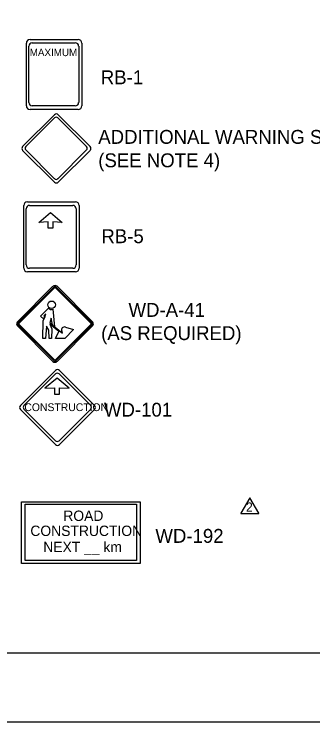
# Model space of a CAD drawing. Extents: x 1381 to 1597, y 125 to 404.
# Drawn here: x 1466.1 to 1512.9, y 124.9 to 235.9 of the extents above; entities that cross this region are included whole.
import ezdxf

# ---------------------------------------------------------------- set-up
doc = ezdxf.new("R2010")
doc.units = 0
for name, color, linetype in [('Level 1', 7, 'Continuous'), ('Level 10', 7, 'Continuous'), ('Level 2', 7, 'Continuous'), ('Level 44', 7, 'Continuous'), ('Level 60', 7, 'Continuous')]:
    doc.layers.add(name, color=color, linetype=linetype)

msp = doc.modelspace()

# ---------------------------------------------------------------- linework, layer by layer
at = {"layer": 'Level 1'}
for p, q in [((1472.17, 193.21), (1466.59, 187.63)), ((1472.3, 193.08), (1466.72, 187.51)), ((1478.25, 187.51), (1472.68, 193.08)), ((1478.38, 187.63), (1472.8, 193.21)), ((1472.42, 192.96), (1466.84, 187.39)), ((1478.13, 187.38), (1472.55, 192.96)), ((1472.23, 190.76), (1472.21, 190.76)), ((1466.59, 187), (1472.17, 181.43)), ((1466.72, 187.13), (1472.29, 181.56)), ((1466.84, 187.25), (1472.42, 181.68)), ((1472.55, 181.68), (1478.13, 187.25)), ((1472.67, 181.56), (1478.25, 187.13)), ((1472.8, 181.43), (1478.38, 187))]:
    msp.add_line(p, q, dxfattribs=at)
for points in [[(1470.76, 188.56), (1470.9, 188.44), (1470.74, 188.04), (1470.23, 188.52), (1471.45, 189.77)], [(1470.76, 188.56), (1470.9, 188.44), (1470.74, 188.04), (1470.23, 188.52), (1471.45, 189.77)], [(1471.18, 186.95), (1471, 185.05), (1470.58, 185.05), (1470.63, 187.78), (1470.74, 188.04), (1470.23, 188.52), (1471.45, 189.77)], [(1474.12, 186.83), (1475.4, 186.44), (1474.02, 185.05), (1472.56, 185.05), (1473.1, 186.1), (1471.69, 187.26), (1471.97, 186.52), (1471.93, 185.05), (1471.58, 185.05), (1471.52, 186.31), (1471.18, 186.95), (1471, 185.05), (1470.58, 185.05), (1470.63, 187.78), (1471.07, 188.88), (1470.76, 188.56)], [(1474.12, 186.83), (1475.4, 186.44), (1474.02, 185.05), (1472.56, 185.05), (1473.1, 186.1), (1471.69, 187.26), (1471.97, 186.52), (1471.93, 185.05), (1471.58, 185.05), (1471.52, 186.31), (1471.18, 186.95), (1471, 185.05), (1470.58, 185.05), (1470.63, 187.78), (1471.07, 188.88), (1470.76, 188.56)], [(1472.15, 189.6), (1472.43, 186.88), (1472.07, 187.18), (1471.86, 188.19), (1471.69, 187.48), (1473.68, 185.84), (1473.54, 186.2)], [(1472.15, 189.6), (1472.43, 186.88), (1472.07, 187.18), (1471.86, 188.19), (1471.69, 187.48), (1473.68, 185.84), (1473.54, 186.2)], [(1472.15, 189.6), (1472.43, 186.88), (1473.68, 185.84), (1473.54, 186.2)], [(1474.12, 186.83), (1475.4, 186.44), (1474.02, 185.05), (1472.56, 185.05), (1473.1, 186.1), (1471.69, 187.26), (1471.97, 186.52), (1471.93, 185.05), (1471.58, 185.05), (1471.52, 186.31), (1471.18, 186.95)]]:
    msp.add_lwpolyline(points, dxfattribs=at)
for points in [[(1470.76, 188.56), (1470.9, 188.44), (1471.07, 188.88)], [(1472.07, 187.17), (1471.86, 188.19), (1471.69, 187.48)]]:
    msp.add_lwpolyline(points, close=True, dxfattribs=at)
msp.add_circle((1471.96, 190.31), 0.591, dxfattribs=at)
msp.add_circle((1471.96, 190.31), 0.591, dxfattribs=at)
msp.add_circle((1471.96, 190.31), 0.591, dxfattribs=at)
for centre, radius, start, end in [((1472.49, 192.89), 0.446, 45, 134.9651), ((1472.49, 192.89), 0.27, 45, 134.9651), ((1472.49, 192.89), 0.0948, 45, 134.9651), ((1471.96, 190.31), 0.734, 226.3135, 284.9576), ((1471.96, 190.31), 0.734, 226.3135, 284.9576), ((1471.96, 190.31), 0.734, 226.3135, 284.9576), ((1466.91, 187.32), 0.446, 134.965, 225), ((1466.91, 187.32), 0.27, 134.965, 225), ((1478.06, 187.32), 0.27, 314.9651, 45), ((1478.06, 187.32), 0.446, 314.9651, 45), ((1466.91, 187.32), 0.0948, 134.965, 225), ((1473.98, 186.37), 0.475, 73.381, 201.0999), ((1473.98, 186.37), 0.475, 73.381, 201.0999), ((1473.98, 186.37), 0.475, 73.381, 201.0999), ((1478.06, 187.32), 0.0948, 314.9651, 45), ((1472.48, 181.75), 0.446, 225, 314.9652), ((1472.48, 181.75), 0.27, 225, 314.9652), ((1472.48, 181.75), 0.0948, 225, 314.9652)]:
    msp.add_arc(centre, radius, start, end, dxfattribs=at)
at = {"layer": 'Level 2'}
for points in [[(1467.22, 159.43), (1485.85, 159.43), (1485.85, 149.77), (1467.22, 149.77)], [(1467.81, 159.05), (1485.23, 159.05), (1485.23, 150.24), (1467.81, 150.24)]]:
    msp.add_lwpolyline(points, close=True, dxfattribs=at)
at = {"layer": 'Level 44'}
for p, q in [((1468.58, 231.89), (1476.1, 231.89)), ((1468, 221.52), (1468, 231.31)), ((1468.39, 222.01), (1468.39, 230.83)), ((1468.91, 231.35), (1475.67, 231.35)), ((1476.2, 230.83), (1476.2, 222.01)), ((1476.68, 231.31), (1476.68, 221.52)), ((1468.39, 222.01), (1468.39, 222.01)), ((1468, 221.51), (1468, 221.52)), ((1476.1, 220.93), (1468.58, 220.93)), ((1468.71, 221.17), (1468.71, 221.17)), ((1475.67, 221.49), (1468.91, 221.49)), ((1472.41, 220.1), (1467.42, 215.11)), ((1477.99, 215.11), (1473, 220.1)), ((1467.91, 215.11), (1472.41, 219.6)), ((1472.94, 219.6), (1477.43, 215.11)), ((1467.42, 214.52), (1472.41, 209.53)), ((1467.42, 214.52), (1467.42, 214.52)), ((1472.41, 210.08), (1467.91, 214.58)), ((1477.43, 214.58), (1472.94, 210.08)), ((1473, 209.53), (1477.99, 214.52)), ((1468.17, 206.44), (1475.69, 206.44)), ((1467.59, 196.06), (1467.59, 205.86)), ((1467.98, 196.56), (1467.98, 205.38)), ((1468.5, 205.9), (1475.27, 205.9)), ((1475.79, 205.38), (1475.79, 196.56)), ((1476.27, 205.86), (1476.27, 196.06)), ((1467.98, 196.55), (1467.98, 196.56)), ((1467.59, 196.06), (1467.59, 196.06)), ((1475.69, 195.48), (1468.17, 195.48)), ((1475.27, 196.03), (1468.5, 196.03)), ((1472.56, 180.03), (1467.07, 174.54)), ((1478.69, 174.54), (1473.21, 180.03)), ((1467.62, 174.53), (1472.56, 179.47)), ((1472.8, 178.83), (1470.91, 177.23)), ((1474.69, 177.23), (1472.8, 178.83)), ((1473.14, 179.47), (1478.08, 174.53)), ((1470.91, 177.23), (1472.42, 177.31)), ((1472.42, 177.31), (1472.42, 176.31)), ((1473.18, 176.31), (1473.18, 177.31)), ((1473.18, 177.31), (1474.69, 177.23)), ((1472.42, 176.31), (1473.17, 176.31)), ((1467.07, 173.89), (1472.56, 168.4)), ((1467.07, 173.89), (1467.07, 173.89)), ((1472.56, 169.01), (1467.62, 173.95)), ((1478.08, 173.95), (1473.14, 169.01)), ((1473.21, 168.4), (1478.69, 173.89))]:
    msp.add_line(p, q, dxfattribs=at)
msp.add_lwpolyline([(1469.96, 203.23), (1471.78, 204.76), (1473.59, 203.23), (1472.14, 203.31), (1472.14, 202.34), (1471.42, 202.34), (1471.42, 203.31)], close=True, dxfattribs=at)
for centre, radius, start, end in [((1468.58, 231.31), 0.58, 90, 180), ((1476.1, 231.31), 0.58, 360, 90), ((1468.91, 230.83), 0.522, 90, 180), ((1475.67, 230.83), 0.522, 360, 90), ((1468.91, 222.01), 0.522, 180, 270), ((1475.67, 222.01), 0.522, 270, 360), ((1468.58, 221.51), 0.58, 180, 270), ((1476.1, 221.51), 0.58, 270, 360), ((1472.7, 219.81), 0.418, 45, 135), ((1472.67, 219.33), 0.376, 45, 135), ((1467.71, 214.82), 0.418, 135, 225), ((1468.18, 214.84), 0.376, 135, 225), ((1477.16, 214.84), 0.376, 315, 45), ((1477.69, 214.82), 0.418, 315, 45), ((1472.67, 210.35), 0.376, 225, 315), ((1472.7, 209.83), 0.418, 225, 315), ((1468.17, 205.86), 0.58, 90, 180), ((1475.69, 205.86), 0.58, 360, 90), ((1468.5, 205.37), 0.522, 90, 180), ((1475.26, 205.37), 0.522, 360, 90), ((1468.5, 196.55), 0.522, 180, 270), ((1475.26, 196.55), 0.522, 270, 360), ((1468.17, 196.06), 0.58, 180, 270), ((1475.69, 196.06), 0.58, 270, 360), ((1472.88, 179.7), 0.459, 45, 135), ((1472.85, 179.18), 0.413, 45, 135), ((1467.39, 174.21), 0.459, 135, 225), ((1467.91, 174.24), 0.413, 135, 225), ((1477.79, 174.24), 0.413, 315, 45), ((1478.37, 174.21), 0.459, 315, 45), ((1472.85, 169.3), 0.413, 225, 315), ((1472.88, 168.73), 0.459, 225, 315)]:
    msp.add_arc(centre, radius, start, end, dxfattribs=at)
at = {"layer": 'Level 60'}
for points in [[(1597.18, 403.94), (1381.18, 403.94), (1381.18, 124.94), (1597.18, 124.94)], [(1578.06, 393.13), (1391.18, 393.13), (1391.18, 135.75), (1578.06, 135.75)]]:
    msp.add_lwpolyline(points, close=True, dxfattribs=at)
for points in [[(1503, 160.07), (1501.61, 157.65)], [(1503, 160.07), (1501.61, 157.65)], [(1504.4, 157.65), (1503, 160.07)], [(1501.61, 157.65), (1501.59, 157.6), (1504.42, 157.6), (1504.4, 157.65)], [(1501.61, 157.65), (1501.59, 157.6), (1504.42, 157.6), (1504.4, 157.65)]]:
    msp.add_lwpolyline(points, dxfattribs=at)

# ---------------------------------------------------------------- texts
at = {"layer": 'Level 10'}
for s, height, p in [('RB-1', 2.178, (1479.66, 224.88)), ('ADDITIONAL WARNING SIGNS AS REQUIRED', 2.177, (1479.26, 215.54)), ('(SEE NOTE 4)', 2.177, (1479.26, 211.87)), ('RB-5', 2.177, (1479.75, 199.97)), ('WD-A-41', 2.177, (1484, 188.42)), ('WD-101', 2.177, (1480.15, 172.78))]:
    msp.add_text(s, height=height, rotation=360, dxfattribs=at).set_placement(p)
for s, p in [('(AS REQUIRED)', (1479.71, 184.78)), ('WD-192', (1488.21, 153))]:
    msp.add_text(s, height=2.177, dxfattribs=at).set_placement(p)
at = {"layer": 'Level 44'}
for s, height, p in [('MAXIMUM', 1.15, (1468.53, 229.29)), ('CONSTRUCTION', 1.2179, (1467.69, 173.65)), ('ROAD', 1.625, (1473.79, 156.43)), ('CONSTRUCTION', 1.625, (1468.63, 154.07))]:
    msp.add_text(s, height=height, rotation=360, dxfattribs=at).set_placement(p)
msp.add_text('NEXT __ km', height=1.625, dxfattribs=at).set_placement((1470.65, 151.54))
at = {"layer": 'Level 60'}
msp.add_text('2', height=1.45, rotation=360, dxfattribs=at).set_placement((1502.38, 157.87))
msp.add_text('2', height=1.45, rotation=360, dxfattribs=at).set_placement((1502.38, 157.87))

doc.saveas('drawing.dxf')
